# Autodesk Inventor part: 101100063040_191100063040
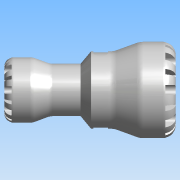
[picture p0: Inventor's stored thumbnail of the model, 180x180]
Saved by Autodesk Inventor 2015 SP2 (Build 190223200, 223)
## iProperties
Created: 2016-12
Part Number: 101100063040_191100063040
Material: PVC-Piping
Description: PLASSON REDUCING COUPLING 63X40 SERIES 1
Document SubType Name: Modeling
Designer: KIM
Mass: 113.204 g
Surface Area: 237.851 cm^2
Volume: 80.8599 cm^3
Density: 1.4 g/cm^3
Appearance: Smooth - White
Author: KIM
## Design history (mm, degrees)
derived "1011.ipt"
feature "Solid1::1011.ipt"
tag "TaggingFeature1"
body "Solid1"
other parameters: "d0" = 183, "d2" = 38.22, "d3" = 63, "d4" = 103, "d5" = 75.6, "d6" = 91, "d7" = 5.25, "d11" = 29.82, "d12" = 71, "d13" = 3.33333, "d14" = 82.4, "d15" = 56, "d16" = 20 deg, "d17" = 20 deg, "d18" = 130 deg, "d22" = 10.96, "d25" = 10.96, "d26" = 0, "d28" = 360 deg, "d30" = 8 deg, "d31" = 1.26, "d32" = 8 deg, "d33" = 1.26, "d35" = 0, "d37" = 360 deg, "d39" = 8, "d42" = 8, "d43" = 0, "d45" = 360 deg, "d47" = 0.8, "d48" = 8 deg, "d49" = 8 deg, "d50" = 0.8, "d52" = 0, "d54" = 360 deg, "d56" = 14, "d57" = 20.6, "d58" = 0.5, "d60" = 12.36, "d61" = 15.75, "d62" = 17.46, "d63" = 0, "d66" = 0, "d68" = 360 deg, "d75" = 10.01969, "d77" = 80.34, "d78" = 1.03, "d_" = 63, "E_" = 103, "H_" = 183, "l_" = 91, "l1" = 71, "Plasson" = 1, "d21" = 13.7, "d23" = 103, "d24" = 75.6, "d59" = 20.03938
